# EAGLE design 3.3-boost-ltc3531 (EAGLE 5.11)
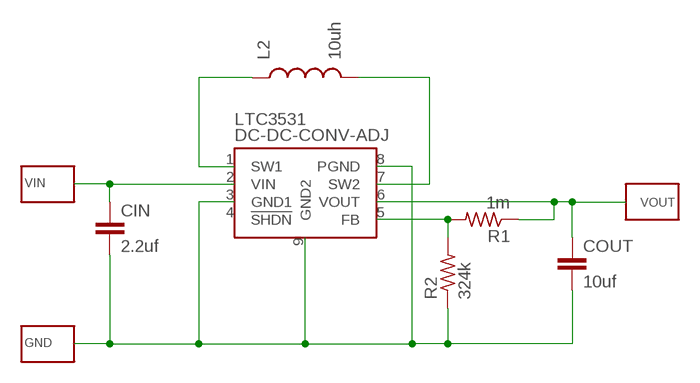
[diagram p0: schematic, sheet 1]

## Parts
CIN  2.2uf  C-EUC1206  [C1206]
COUT  10uf  C-EUC1206  [C1206]
DC-DC-CONV-ADJ  LTC3531  [DFN8-POWERPAD]
GND  WIREPAD-SMD-NO-VALUE  [WIREPAD-SMD]
L2  10uh  INDUCTOR1210  [1210]
R1  1m  R-US_R0603  [R0603]
R2  324k  R-US_R0603  [R0603]
VIN  WIREPAD-SMD-NO-VALUE  [WIREPAD-SMD]
VOUT  WIREPAD-SMD-NO-VALUE  [WIREPAD-SMD]

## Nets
N$1: COUT.1 DC-DC-CONV-ADJ.6(VOUT) R1.1 VOUT.1(P)
N$2: CIN.1 DC-DC-CONV-ADJ.2(VIN) VIN.1(P)
N$4: DC-DC-CONV-ADJ.5(FB) R1.2 R2.2
N$6: CIN.2 COUT.2 DC-DC-CONV-ADJ.3(GND1) DC-DC-CONV-ADJ.8(PGND) DC-DC-CONV-ADJ.9(GND2) GND.1(P) R2.1
N$7: DC-DC-CONV-ADJ.1(SW1) L2.1
N$8: DC-DC-CONV-ADJ.7(SW2) L2.2
Unconnected: DC-DC-CONV-ADJ.4(!SHDN)

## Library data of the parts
CIN COUT = rcl:C-EU: CAPACITOR, European symbol
DC-DC-CONV-ADJ = trl:LTC3531
GND VIN VOUT = trl:WIREPAD-SMD-NO-VALUE
L2 = SparkFun:INDUCTOR: Inductors
R1 R2 = resistor:R-US_: RESISTOR, American symbol

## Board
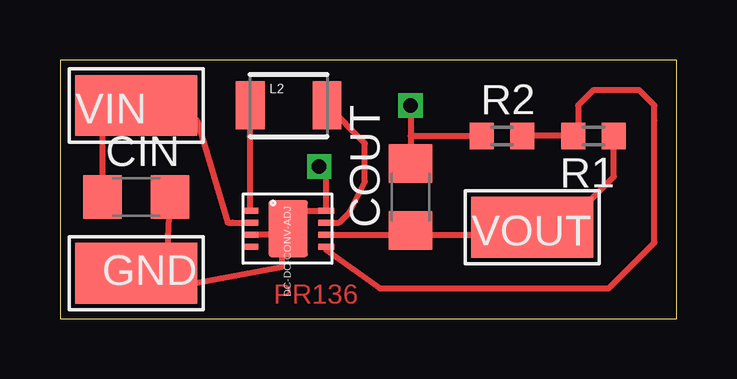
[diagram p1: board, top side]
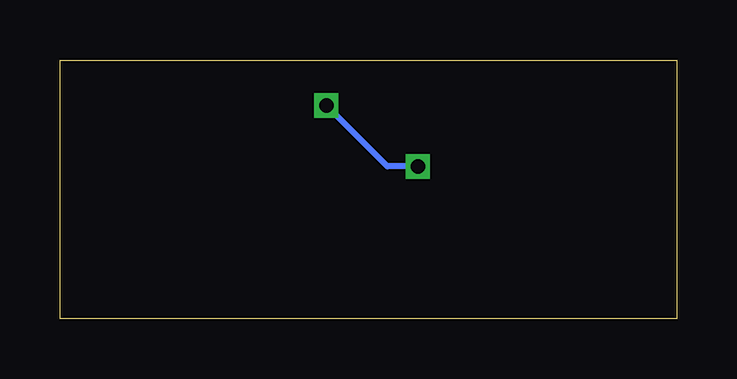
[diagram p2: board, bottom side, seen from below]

Size 25.7 x 10.79 mm. Coordinates in mm from the lower left corner, seen from the top.
Outline: 0,0 25.7,0 25.7,10.79 0,10.79 0,0
Copper layers (1*16): Top 0.035mm / dielectric 1.5mm / Bottom 0.035mm
Design rules "default": minimum track width 10mil, minimum drill 24mil, track to track 8mil, track to pad 8mil, pad to pad 8mil, via to via 8mil, smd to smd 8mil, copper to edge 40mil, drill to drill 8mil, minimum pad ring 10mil, minimum via ring 8mil, stop-mask expansion 4mil, vias tented up to drill 0mil, thermal gap 10mil

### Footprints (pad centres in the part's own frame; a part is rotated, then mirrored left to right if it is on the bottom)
C1206 = smd 1.6 x 1.8: 1 -1.4,0; 2 1.4,0
DFN8-POWERPAD = smd 0.25 x 0.67: 1 -0.7,-1.6; 2 -0.2,-1.6; 3 0.3,-1.6; 4 0.8,-1.6; 5 0.8,1.56; 6 0.3,1.56; 7 -0.2,1.56; 8 -0.7,1.56 | smd 2.38 x 1.65: 9 0.05,-0.02
WIREPAD-SMD = smd 2.54 x 5.08: 1 0,0
1210 = smd 1.2 x 2: 1 -1.6,0; 2 1.6,0
R0603 = smd 1 x 1.1: 1 -0.85,0; 2 0.85,0

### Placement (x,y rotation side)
CIN  3.17,5.08 0 top
COUT  14.61,5.08 90 top
DC-DC-CONV-ADJ  9.53,3.81 270 top
GND  3.17,1.91 90 top
L2  9.53,8.89 0 top
R1  22.23,7.62 180 top
R2  18.41,7.62 0 top
VIN  3.17,8.89 270 top
VOUT  19.68,3.81 270 top

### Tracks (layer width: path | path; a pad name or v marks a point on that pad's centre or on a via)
N$1
  Top 0.254: COUT.1 14.44,3.51 DC-DC-CONV-ADJ.6 19.39,3.51 VOUT.1 20.95,3.81 23.07,5.93 R1.1
N$2
  Top 0.254: DC-DC-CONV-ADJ.2 7.18,4.01 6.99,4.01 5.71,8.26 VIN.1 1.77,8.12 CIN.1
N$4
  Top 0.254: R2.2 R1.2 21.59,7.83 21.59,8.89 22.23,9.53 24.13,9.53 24.77,8.89 24.77,8.26 24.77,3.17 22.86,1.27 13.34,1.27 11.09,2.88 DC-DC-CONV-ADJ.5
N$6  (via drill 0.6)
  Top 0.254: 9.26,3.51 DC-DC-CONV-ADJ.3 | 9.26,3.51 DC-DC-CONV-ADJ.9 10.26,4.51 DC-DC-CONV-ADJ.8 11.09,6.06 v10.79,6.35 | 9.26,3.51 9.26,2.17 4.45,1.27 5.08,1.27 5.08,1.91 GND.1 4.45,1.91 4.45,2.54 CIN.2 | v14.61,8.89 14.61,7.62 | 14.61,7.62 COUT.2 | 14.61,7.62 R2.1
  Bottom 0.254: v10.79,6.35 12.06,6.35 v14.61,8.89
N$7
  Top 0.254: DC-DC-CONV-ADJ.1 L2.1
N$8
  Top 0.254: DC-DC-CONV-ADJ.7 11.63,4.01 12.06,4.45 12.7,5.71 12.7,7.32 L2.2

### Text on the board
Top: PR136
